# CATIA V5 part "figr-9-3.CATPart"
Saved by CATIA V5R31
Part number: Part1
Bounding box of the stored display mesh (mm): x -25 to 69.61, y -164.735 to 0, z 0 to 45
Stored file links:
  D:\PROJECTS\Project 2021\US EDITION\CATIA V5 6R 2021\Resources\Part Files\c09_catia_v5_6r2021_prt\c09_catia_v5_6r2021_prt\figr-9-3.CATPart
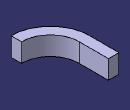
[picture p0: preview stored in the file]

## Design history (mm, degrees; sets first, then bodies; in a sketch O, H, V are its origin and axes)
Body1 (main body)
  Sketch1 on xy-plane, origin (0, 0, 0), H (1, 0, 0), V (0, 1, 0)
    line L1 (0, 0) -> (0, -70.1255)
    arc A1 centre (69.6095, -70.1255) radius 69.6095 from (0, -70.1255) to (69.6095, -139.7351) ccw
    vertical: L1 V
    tangency: A1 L1
  Sketch2 on zx-plane, origin (0, 0, 0), H (-1, 0, 0), V (0, 0, 1)
    point P1 (0, 0)
    line L1 (0, 0) -> (25, 0)
    line L2 (25, 0) -> (25, 45)
    line L3 (25, 45) -> (0, 45)
    line L4 (0, 45) -> (0, 0)
    length L3 = 25
    length L2 = 45
    coincidence: P1 H, P1 O
    horizontal: L1 H, L3 H
    vertical: L2 V, L4 V
  Rib1: profile Sketch2, centre curve Sketch1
